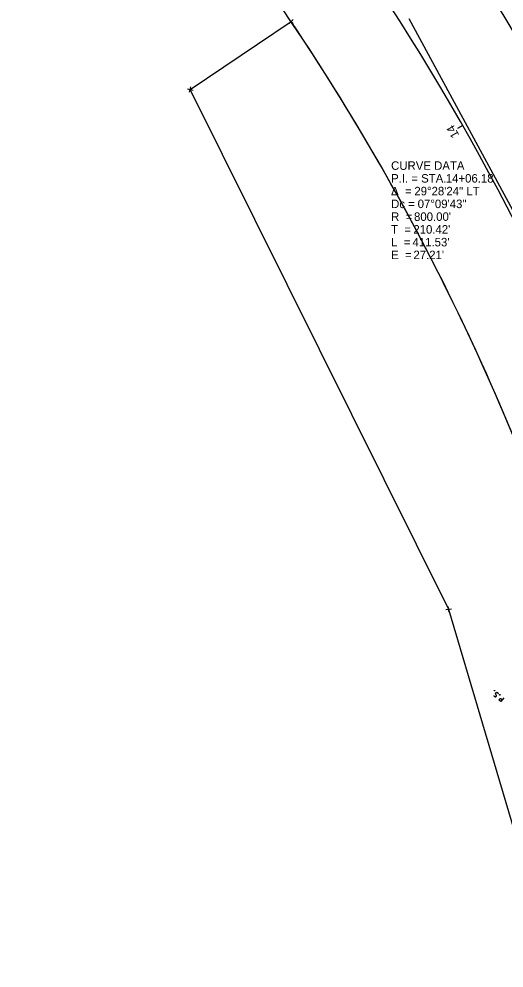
# Model space of a CAD drawing. Extents: x 2392034 to 2394211, y 184331 to 186655.
# Drawn here: x 2392631.5 to 2392791, y 185199.4 to 185511.7 of the extents above; entities that cross this region are included whole.
import ezdxf

# ---------------------------------------------------------------- set-up
doc = ezdxf.new("R2010")
doc.units = 0
for name, color, linetype in [('V-ROAD-SIGN', 7, 'Continuous'), ('V-SITE-MAIL', 7, 'Continuous'), ('V-SITE-POST', 7, 'Continuous'), ('V-SURV-ANNO', 7, 'Continuous'), ('V-TOPO-ANNO', 7, 'Continuous'), ('V-TOPO-TINN', 7, 'Continuous'), ('V-TOPO-WSHD', 7, 'Continuous'), ('V-UTIL-NGAS-STRC', 7, 'Continuous'), ('V-UTIL-STRM-STRC', 7, 'Continuous')]:
    doc.layers.add(name, color=color, linetype=linetype)

msp = doc.modelspace()

# ---------------------------------------------------------------- linework, layer by layer
at = {"layer": 'V-ROAD-SIGN'}
for radius, end in [(830, 45.41914), (770, 44.49359)]:
    msp.add_arc((2392082.2, 185080.9), radius, 15.02013, end, dxfattribs=at)
at = {"layer": 'V-SITE-MAIL'}
msp.add_arc((2392082.2, 185080.9), 800, 15.02013, 44.49359, dxfattribs=at)
at = {"layer": 'V-SURV-ANNO'}
msp.add_line((2392777.47, 185476.63), (2392775.73, 185475.64), dxfattribs=at)
at = {"layer": 'V-TOPO-ANNO'}
msp.add_line((2392806.01, 185426.43), (2392759.81, 185511.73), dxfattribs=at)
msp.add_line((2392806.01, 185426.43), (2392759.81, 185511.73), dxfattribs=at)
at = {"layer": 'V-TOPO-TINN'}
for points in [[(2392787.7, 185289.09), (2392787.7, 185289.05), (2392787.71, 185289.01), (2392787.76, 185288.92), (2392787.84, 185288.83), (2392787.91, 185288.77), (2392787.94, 185288.75), (2392788.07, 185288.69), (2392788.21, 185288.67), (2392788.34, 185288.7), (2392788.42, 185288.77), (2392788.46, 185288.83), (2392788.51, 185288.92), (2392788.5, 185289.04), (2392788.26, 185289.72), (2392788.25, 185289.79), (2392788.27, 185289.84), (2392788.3, 185289.92), (2392788.35, 185289.97), (2392788.4, 185290.03), (2392788.44, 185290.06), (2392788.5, 185290.09), (2392788.55, 185290.12), (2392788.59, 185290.13), (2392788.64, 185290.14), (2392788.68, 185290.14), (2392788.73, 185290.13), (2392788.76, 185290.12), (2392788.85, 185290.07), (2392788.97, 185289.97), (2392789.03, 185289.89), (2392789.09, 185289.73), (2392789.11, 185289.62)], [(2392787.86, 185290.59), (2392787.82, 185290.62), (2392787.81, 185290.67), (2392787.82, 185290.73), (2392787.86, 185290.77), (2392787.92, 185290.79), (2392787.96, 185290.79), (2392788, 185290.76), (2392788.01, 185290.72), (2392788, 185290.66), (2392787.96, 185290.61), (2392787.91, 185290.59), (2392787.86, 185290.59)], [(2392790.97, 185288.35), (2392789.97, 185287.11), (2392789.56, 185287.44), (2392789.52, 185287.48), (2392789.48, 185287.55), (2392789.47, 185287.59), (2392789.46, 185287.63), (2392789.46, 185287.71), (2392789.48, 185287.78), (2392789.52, 185287.87), (2392789.62, 185287.99), (2392789.66, 185288.02), (2392789.72, 185288.07), (2392789.81, 185288.11), (2392789.87, 185288.11), (2392789.91, 185288.11), (2392789.97, 185288.09), (2392790.05, 185288.05), (2392790.46, 185287.71)], [(2392789.56, 185289.22), (2392789.52, 185289.25), (2392789.51, 185289.29), (2392789.52, 185289.35), (2392789.55, 185289.4), (2392789.61, 185289.42), (2392789.65, 185289.42), (2392789.7, 185289.38), (2392789.71, 185289.34), (2392789.7, 185289.28), (2392789.66, 185289.23), (2392789.6, 185289.22), (2392789.56, 185289.22)]]:
    msp.add_lwpolyline(points, dxfattribs=at)
at = {"layer": 'V-TOPO-WSHD'}
for p, q in [((2392687.79, 185488.53), (2392720.98, 185510.86)), ((2392772.83, 185317.42), (2392687.79, 185488.53)), ((2392807.77, 185199.41), (2392772.83, 185317.42))]:
    msp.add_line(p, q, dxfattribs=at)
at = {"layer": 'V-UTIL-NGAS-STRC'}
for p, q in [((2392720.31, 185510.2), (2392721.64, 185511.53)), ((2392720.31, 185511.53), (2392721.64, 185510.2)), ((2392686.87, 185488.71), (2392688.72, 185488.35)), ((2392687.61, 185487.6), (2392687.97, 185489.45)), ((2392772.97, 185316.48), (2392772.68, 185318.35)), ((2392773.76, 185317.56), (2392771.9, 185317.27))]:
    msp.add_line(p, q, dxfattribs=at)
at = {"layer": 'V-UTIL-STRM-STRC'}
for p, q in [((2392687.79, 185488.53), (2392720.98, 185510.86)), ((2392772.83, 185317.42), (2392687.79, 185488.53)), ((2392807.77, 185199.41), (2392772.83, 185317.42))]:
    msp.add_line(p, q, dxfattribs=at)
msp.add_arc((2392082.2, 185080.9), 770, 16.39806, 33.9449, dxfattribs=at)

# ---------------------------------------------------------------- texts
at = {"layer": 'V-SITE-POST'}
for s, p in [('CURVE DATA', (2392753.87, 185462.09)), ('P.I. = STA. ', (2392753.87, 185457.89)), ('14+06.18', (2392771.86, 185457.89)), ('Δ  = ', (2392753.87, 185453.69)), ('29°28\'24" LT', (2392761.52, 185453.69)), ('Dc = ', (2392753.87, 185449.49)), ('07°09\'43"', (2392762.61, 185449.49)), ('R  = ', (2392753.87, 185445.29)), ("800.00'", (2392761.41, 185445.29)), ('T  = ', (2392753.87, 185441.09)), ("210.42'", (2392761.19, 185441.09)), ("411.53'", (2392760.91, 185436.89)), ('L  = ', (2392753.87, 185436.89)), ('E  = ', (2392753.87, 185432.69)), ("27.21'", (2392761.21, 185432.69))]:
    msp.add_text(s, height=2.8, dxfattribs=at).set_placement(p)
at = {"layer": 'V-SURV-ANNO'}
msp.add_text('14', height=2.8, rotation=119.6477, dxfattribs=at).set_placement((2392776.37, 185473.52))

doc.saveas('drawing.dxf')
